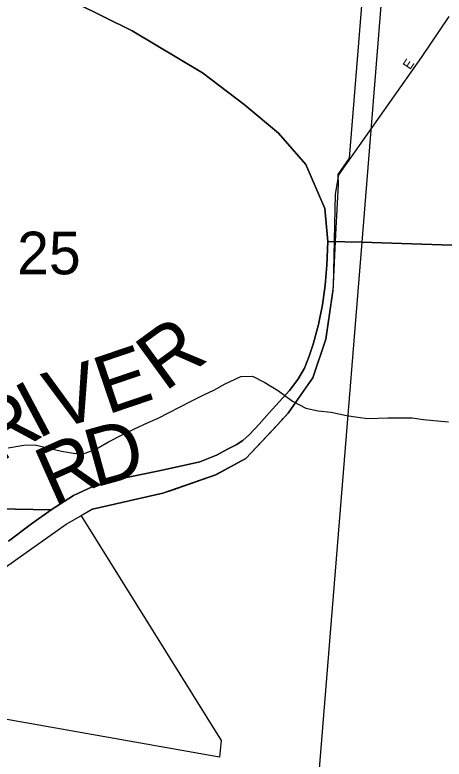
# Model space of a CAD drawing. Extents: x 0 to 34, y -2.3 to 22.
# Drawn here: x 7.813 to 8.234, y 15.127 to 15.857 of the extents above; entities that cross this region are included whole.
import ezdxf

# ---------------------------------------------------------------- set-up
doc = ezdxf.new("R2010")
doc.units = 0
for name, color, linetype in [('GM_X_City_Street', 7, 'Continuous'), ('GM_X_City_Street_Text', 7, 'Continuous'), ('GM_X_Corporation', 7, 'Continuous'), ('GM_X_County_Road', 7, 'Continuous'), ('GM_X_County_Road_Text', 7, 'Continuous'), ('GM_X_Minor_River', 7, 'Continuous'), ('GM_X_Section', 7, 'Continuous'), ('GM_X_Section_Text', 7, 'Continuous')]:
    doc.layers.add(name, color=color, linetype=linetype)

msp = doc.modelspace()

# ---------------------------------------------------------------- linework, layer by layer
at = {"layer": 'GM_X_City_Street'}
for p, q in [((8.21185, 15.81576), (8.23893, 15.85587)), ((8.13073, 15.70037), (8.21185, 15.81576)), ((8.12766, 15.68143), (8.13073, 15.70037)), ((8.12571, 15.59061), (8.12766, 15.68143)), ((8.11815, 15.53945), (8.12571, 15.59061)), ((8.10518, 15.50132), (8.11815, 15.53945)), ((8.08126, 15.46684), (8.10518, 15.50132)), ((8.07638, 15.4616), (8.08126, 15.46684))]:
    msp.add_line(p, q, dxfattribs=at)
at = {"layer": 'GM_X_Corporation'}
for p, q in [((8.21766, 16.68484), (8.14105, 15.71671)), ((8.14105, 15.71671), (8.12989, 15.70075)), ((8.12989, 15.70075), (8.13, 15.69103)), ((8.13, 15.69103), (8.1275, 15.64208)), ((8.1275, 15.64208), (8.125, 15.58686)), ((8.125, 15.58686), (8.11815, 15.53945)), ((8.11815, 15.53945), (8.10518, 15.50132)), ((8.10518, 15.50132), (8.0987, 15.49215)), ((8.0987, 15.49215), (8.08126, 15.46685)), ((8.08126, 15.46685), (8.06694, 15.45145)), ((8.06694, 15.45145), (8.03965, 15.4221)), ((8.03965, 15.4221), (8.01005, 15.40637)), ((8.01005, 15.40637), (7.95837, 15.38807)), ((7.95837, 15.38807), (7.88926, 15.37241)), ((7.88926, 15.37241), (7.87823, 15.36613)), ((7.87823, 15.36613), (8.01561, 15.14574)), ((8.01367, 15.12916), (7.77433, 15.17172)), ((8.01561, 15.14574), (8.01367, 15.12916))]:
    msp.add_line(p, q, dxfattribs=at)
at = {"layer": 'GM_X_County_Road'}
for p, q in [((8.03965, 15.42209), (8.07455, 15.45963)), ((8.07455, 15.45963), (8.07638, 15.4616)), ((8.01006, 15.40637), (8.03965, 15.42209)), ((7.97205, 15.39291), (8.01006, 15.40637)), ((7.95837, 15.38807), (7.96944, 15.39199)), ((7.96944, 15.39199), (7.97205, 15.39291)), ((7.88926, 15.37241), (7.95837, 15.38807)), ((7.86349, 15.35774), (7.88926, 15.37241)), ((7.7956, 15.30974), (7.86349, 15.35774))]:
    msp.add_line(p, q, dxfattribs=at)
at = {"layer": 'GM_X_Minor_River'}
for p, q in [((8.01931, 15.49547), (8.03471, 15.50267)), ((8.03471, 15.50267), (8.04613, 15.50312)), ((8.04613, 15.50312), (8.05811, 15.49671)), ((8.00812, 15.48931), (8.01931, 15.49547)), ((8.05811, 15.49671), (8.07158, 15.48873)), ((7.98655, 15.47885), (7.99849, 15.48462)), ((7.99849, 15.48462), (8.00812, 15.48931)), ((8.07158, 15.48873), (8.08536, 15.47846)), ((7.9746, 15.4727), (7.98655, 15.47885)), ((8.08536, 15.47846), (8.09848, 15.47164)), ((7.96457, 15.46726), (7.9746, 15.4727)), ((8.09848, 15.47164), (8.11057, 15.46903)), ((7.95378, 15.46185), (7.96457, 15.46726)), ((8.11057, 15.46903), (8.12345, 15.46754)), ((8.12345, 15.46754), (8.13819, 15.46448)), ((8.13819, 15.46448), (8.14954, 15.46265)), ((8.14954, 15.46265), (8.15902, 15.46163)), ((7.92992, 15.45107), (7.94378, 15.45755)), ((7.94378, 15.45755), (7.95378, 15.46185)), ((8.15902, 15.46163), (8.1689, 15.46175)), ((8.1689, 15.46175), (8.17918, 15.46223)), ((8.17918, 15.46223), (8.19286, 15.46224)), ((8.19286, 15.46224), (8.20274, 15.46197)), ((8.20274, 15.46197), (8.21372, 15.46054)), ((8.21372, 15.46054), (8.22396, 15.4595)), ((8.22396, 15.4595), (8.23837, 15.45835)), ((7.91836, 15.44529), (7.92992, 15.45107)), ((7.90487, 15.43843), (7.91836, 15.44529)), ((7.80665, 15.43271), (7.82193, 15.43534)), ((7.82193, 15.43534), (7.83296, 15.4358)), ((7.83296, 15.4358), (7.84655, 15.43239)), ((7.89252, 15.43153), (7.90487, 15.43843)), ((7.84655, 15.43239), (7.85901, 15.42939)), ((7.85901, 15.42939), (7.87264, 15.42712)), ((7.87264, 15.42712), (7.88215, 15.42762)), ((7.88215, 15.42762), (7.89252, 15.43153))]:
    msp.add_line(p, q, dxfattribs=at)
at = {"layer": 'GM_X_Section'}
for p, q in [((8.22968, 16.5747), (8.15324, 15.63433)), ((8.22968, 16.5747), (8.15324, 15.63433)), ((7.92805, 15.84176), (7.87261, 15.86917)), ((7.87261, 15.86917), (7.92805, 15.84176)), ((7.99718, 15.80041), (7.92805, 15.84176)), ((7.92805, 15.84176), (7.99718, 15.80041)), ((8.03815, 15.76954), (7.99718, 15.80041)), ((7.99718, 15.80041), (8.03815, 15.76954)), ((8.07159, 15.7415), (8.03815, 15.76954)), ((8.03815, 15.76954), (8.07159, 15.7415)), ((8.09854, 15.71058), (8.07159, 15.7415)), ((8.07159, 15.7415), (8.09854, 15.71058)), ((8.11725, 15.66735), (8.09854, 15.71058)), ((8.09854, 15.71058), (8.11725, 15.66735)), ((8.11992, 15.63508), (8.11725, 15.66735)), ((8.11725, 15.66735), (8.11992, 15.63508)), ((8.15324, 15.63433), (8.07193, 14.63004)), ((8.15324, 15.63433), (8.07193, 14.63004)), ((8.11992, 15.63508), (8.11901, 15.612)), ((8.11901, 15.612), (8.11992, 15.63508)), ((8.15324, 15.63433), (8.11992, 15.63508)), ((8.11992, 15.63508), (8.15324, 15.63433)), ((8.15324, 15.63433), (8.87917, 15.61026)), ((8.87917, 15.61026), (8.15324, 15.63433)), ((8.11901, 15.612), (8.11743, 15.59234)), ((8.11743, 15.59234), (8.11901, 15.612)), ((8.11743, 15.59234), (8.11472, 15.57308)), ((8.11472, 15.57308), (8.11743, 15.59234)), ((8.11472, 15.57308), (8.11086, 15.55384)), ((8.11086, 15.55384), (8.11472, 15.57308)), ((8.11086, 15.55384), (8.10549, 15.53427)), ((8.10549, 15.53427), (8.11086, 15.55384)), ((8.10549, 15.53427), (8.10182, 15.52261)), ((8.10182, 15.52261), (8.10549, 15.53427)), ((8.10182, 15.52261), (8.097, 15.51098)), ((8.097, 15.51098), (8.10182, 15.52261)), ((8.097, 15.51098), (8.09069, 15.49976)), ((8.09069, 15.49976), (8.097, 15.51098)), ((8.09069, 15.49976), (8.08249, 15.48896)), ((8.08249, 15.48896), (8.09069, 15.49976)), ((8.08249, 15.48896), (8.07238, 15.47783)), ((8.07238, 15.47783), (8.08249, 15.48896)), ((8.07238, 15.47783), (8.06267, 15.46707)), ((8.06267, 15.46707), (8.07238, 15.47783)), ((8.06267, 15.46707), (8.05256, 15.45593)), ((8.05256, 15.45593), (8.06267, 15.46707)), ((8.05256, 15.45593), (8.04324, 15.44592)), ((8.04324, 15.44592), (8.05256, 15.45593)), ((8.04324, 15.44592), (8.03667, 15.44)), ((8.03667, 15.44), (8.04324, 15.44592)), ((8.03012, 15.43561), (8.02246, 15.43162)), ((8.02246, 15.43162), (8.03012, 15.43561)), ((8.03667, 15.44), (8.03012, 15.43561)), ((8.03012, 15.43561), (8.03667, 15.44)), ((8.02246, 15.43162), (8.01095, 15.42544)), ((8.01095, 15.42544), (8.02246, 15.43162)), ((7.99452, 15.419), (7.98156, 15.41588)), ((7.98156, 15.41588), (7.99452, 15.419)), ((8.01095, 15.42544), (7.99452, 15.419)), ((7.99452, 15.419), (8.01095, 15.42544)), ((7.98156, 15.41588), (7.95302, 15.40972)), ((7.95302, 15.40972), (7.98156, 15.41588)), ((7.92599, 15.40428), (7.90658, 15.40017)), ((7.90658, 15.40017), (7.92599, 15.40428)), ((7.95302, 15.40972), (7.92599, 15.40428)), ((7.92599, 15.40428), (7.95302, 15.40972)), ((7.90658, 15.40017), (7.88902, 15.39451)), ((7.88902, 15.39451), (7.90658, 15.40017)), ((7.88902, 15.39451), (7.87065, 15.38584)), ((7.87065, 15.38584), (7.88902, 15.39451)), ((7.87065, 15.38584), (7.84873, 15.37195)), ((7.84873, 15.37195), (7.87065, 15.38584)), ((7.84873, 15.37195), (7.58974, 15.37712)), ((7.58974, 15.37712), (7.84873, 15.37195)), ((7.82947, 15.358), (7.84873, 15.37195)), ((7.84873, 15.37195), (7.82947, 15.358)), ((7.80711, 15.34108), (7.82947, 15.358)), ((7.82947, 15.358), (7.80711, 15.34108))]:
    msp.add_line(p, q, dxfattribs=at)

# ---------------------------------------------------------------- texts
at = {"layer": 'GM_X_City_Street_Text'}
msp.add_text('E', height=0.00947, rotation=56.31413, dxfattribs=at).set_placement((8.20065, 15.80299))
at = {"layer": 'GM_X_County_Road_Text'}
for s, rotation, p in [('R', 36.07267, (7.96014, 15.48707)), ('E', 18.73985, (7.90357, 15.46495)), ('V', 16.18808, (7.85297, 15.4502)), ('I', 27.95195, (7.83521, 15.44042)), ('R', 31.69354, (7.79635, 15.41639)), ('D', 15.45152, (7.89135, 15.39362)), ('R', 23.94901, (7.85079, 15.37543))]:
    msp.add_text(s, height=0.05682, rotation=rotation, dxfattribs=at).set_placement(p)
at = {"layer": 'GM_X_Section_Text'}
msp.add_text('25', height=0.041856, rotation=0.00001, dxfattribs=at).set_placement((7.81547, 15.6029))

doc.saveas('drawing.dxf')
